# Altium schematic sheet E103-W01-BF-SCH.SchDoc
size A4
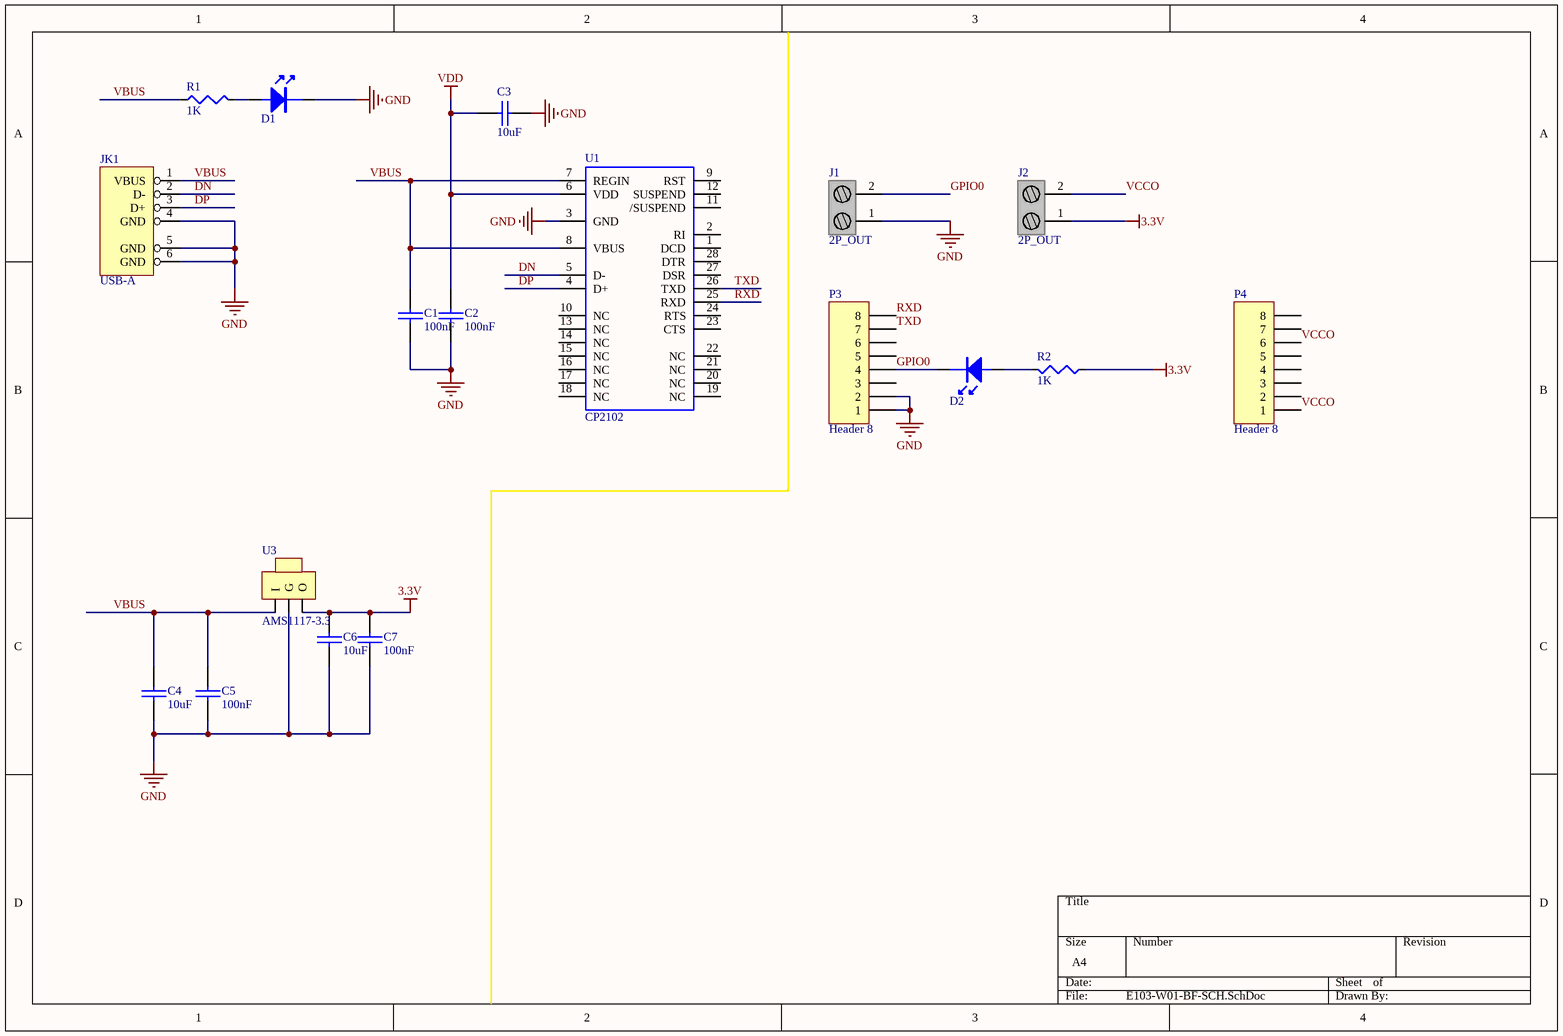
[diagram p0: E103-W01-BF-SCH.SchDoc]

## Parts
C1  100nF  [0603]
C2  100nF  [0603]
C3  10uF  [0603]
C4  10uF  [0603]
C5  100nF  [0603]
C6  10uF  [0603]
C7  100nF  [0603]
D1  LED  [LED0805]  (value not drawn)
D2  LED  [LED0805]  (value not drawn)
J1  2P_OUT  [HDR1X2]
J2  2P_OUT  [HDR1X2]
JK1  USB-A  [USB-AG-DIP]
P3  Header 8  [HDR1X8-2.0]
P4  Header 8  [HDR1X8-2.0]
R1  1K  [0603]
R2  1K  [0603]
U1  CP2102  [QFN28]
U3  AMS1117-3.3  [SOT-223]

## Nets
3.3V: C6.1 C7.1 J2.1(VDD) R2.1 U3.2(O)
GND: C1.2 C2.2 C3.2 C4.2 C5.2 C6.2 C7.2 D1.K J1.1(VDD) JK1.4(GND) JK1.5(GND) JK1.6(GND) P3.1 P3.2 U1.3(GND) U3.1(G)
VDD: C2.1 C3.1 U1.6(VDD)
DN: JK1.2(D-) U1.5(D-)
DP: JK1.3(D+) U1.4(D+)
GPIO0: D2.K J1.2(VDD) P3.4
RXD: P3.8 U1.25(RXD)
TXD: P3.7 U1.26(TXD)
VBUS: C1.1 C4.1 C5.1 JK1.1(VBUS) R1.1 U1.7(REGIN) U1.8(VBUS) U3.3(I)
VCCO: J2.2(VDD) P4.1 P4.6
NetD1_A: D1.A R1.2
NetD2_A: D2.A R2.2

Not connected (* = marked no-connect by the designer): P3 3 5 6; P4 2 3 4 5 7 8; U1 1(DCD) 2(RI) 9(RST) 10(NC) 11(/SUSPEND) 12(SUSPEND) 13(NC) 14(NC) 15(NC) 16(NC) 17(NC) 18(NC) 19(NC) 20(NC) 21(NC) 22(NC) 23(CTS) 24(RTS) 27(DSR) 28(DTR)

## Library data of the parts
C1-C7 = cap0603: Capacitor
P3 P4 = Header 8: Header, 8-Pin
R1 R2 = res0603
